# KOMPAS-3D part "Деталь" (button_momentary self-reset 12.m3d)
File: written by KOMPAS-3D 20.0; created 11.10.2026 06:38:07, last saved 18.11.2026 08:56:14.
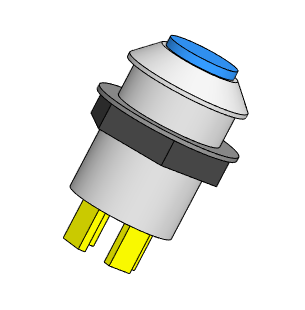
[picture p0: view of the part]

Document properties: Полное имя файла: D:\RicWork\Project-EPS32\box_compas\переключатели и кнопки\button_momentary self-reset 12.m3d

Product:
- Part/product: Деталь
    Масса: 0.0186011

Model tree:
1. Эскиз:1
2. Элемент выдавливания:1
     Расстояние 1 = 3
3. Фаска:1  (with: Элемент выдавливания:1)
     Угол = 45; Длина 1 = 2.5; Длина 2 = 2.5
4. Эскиз:2  (with: Элемент выдавливания:1)
5. Элемент выдавливания:2
     Расстояние 1 = 1
6. Эскиз:3  (with: Элемент выдавливания:1)
7. Элемент выдавливания:3
     Расстояние 1 = 15
8. Смещенная плоскость:1  (with: Элемент выдавливания:1)
     Расстояние = 4.5
9. Эскиз:4
10. Элемент выдавливания:4
     Расстояние 1 = 3
11. Эскиз:5  (with: Элемент выдавливания:3)
12. Элемент выдавливания:5
     Расстояние 1 = 5
13. Массив по концентрической сетке:1  (with: Элемент выдавливания:5, Эскиз:5, Элемент выдавливания:3)  (4 pattern instances)
     Шаг 2 = 360
14. Эскиз:6  (with: Элемент выдавливания:3)
15. Элемент выдавливания:6
     Расстояние 1 = 0.5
